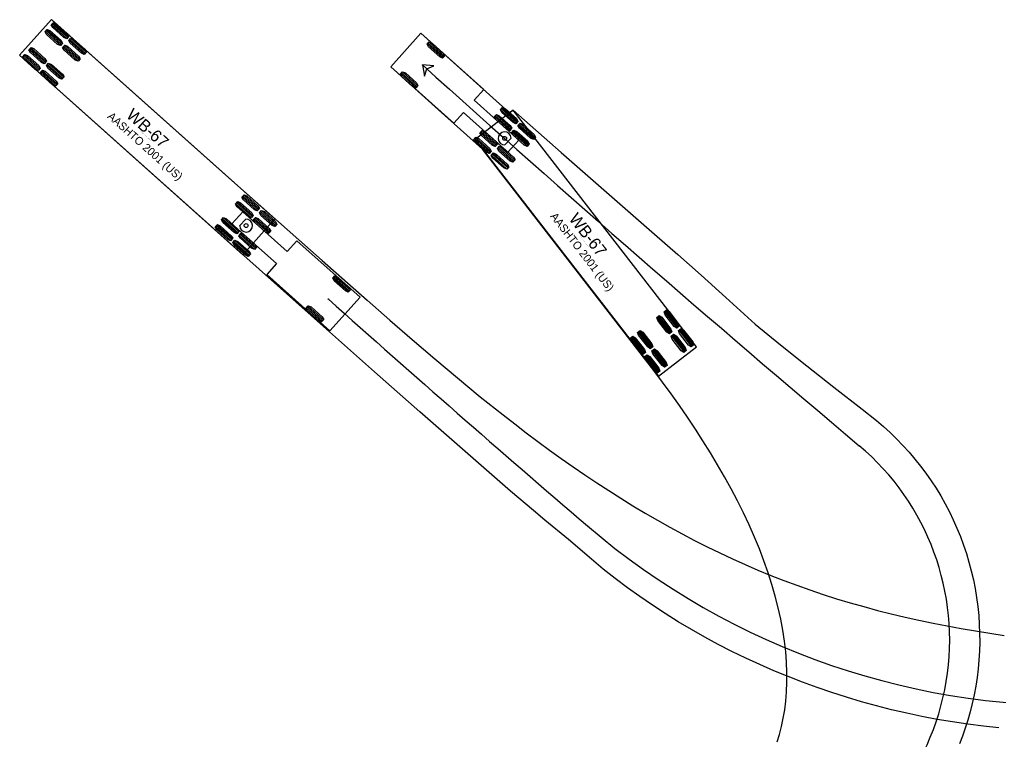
# Model space of a CAD drawing. Extents: x 1639988 to 1641860, y 841974 to 844187.
# Drawn here: x 1641375.4 to 1641548.8, y 842139 to 842266.5 of the extents above; entities that cross this region are included whole.
import ezdxf

# ---------------------------------------------------------------- set-up
doc = ezdxf.new("R2010")
doc.units = 0
doc.layers.add('Scratch_Level_1', color=7, linetype='Continuous')

msp = doc.modelspace()

# ---------------------------------------------------------------- linework, layer by layer
at = {"layer": 'Scratch_Level_1'}
for p, q in [((1641381.1, 842266.48), (1641375.43, 842260.15)), ((1641383.81, 842263.14), (1641381.07, 842265.58)), ((1641420.61, 842231.16), (1641381.1, 842266.48)), ((1641383.96, 842263.31), (1641381.23, 842265.75)), ((1641384.11, 842263.48), (1641381.38, 842265.92)), ((1641382.71, 842261.91), (1641379.97, 842264.35)), ((1641382.86, 842262.08), (1641380.13, 842264.52)), ((1641383.01, 842262.25), (1641380.28, 842264.69)), ((1641446.48, 842264.1), (1641441.14, 842258.14)), ((1641457.65, 842254.09), (1641446.48, 842264.1)), ((1641386.12, 842259.47), (1641383.38, 842261.92)), ((1641386.91, 842260.36), (1641384.18, 842262.81)), ((1641387.07, 842260.53), (1641384.33, 842262.98)), ((1641387.22, 842260.7), (1641384.48, 842263.15)), ((1641447.64, 842262.14), (1641450.36, 842259.69)), ((1641447.79, 842262.31), (1641450.51, 842259.86)), ((1641447.94, 842262.48), (1641450.67, 842260.03)), ((1641375.43, 842260.15), (1641414.94, 842224.82)), ((1641378.9, 842257.66), (1641376.17, 842260.1)), ((1641379.06, 842257.83), (1641376.32, 842260.27)), ((1641379.85, 842258.72), (1641377.12, 842261.16)), ((1641380, 842258.89), (1641377.27, 842261.33)), ((1641380.16, 842259.06), (1641377.42, 842261.5)), ((1641385.81, 842259.13), (1641383.08, 842261.58)), ((1641385.97, 842259.3), (1641383.23, 842261.75)), ((1641378.75, 842257.49), (1641376.02, 842259.93)), ((1641382.96, 842255.94), (1641380.22, 842258.38)), ((1641383.11, 842256.11), (1641380.38, 842258.55)), ((1641383.26, 842256.28), (1641380.53, 842258.72)), ((1641381.86, 842254.71), (1641379.12, 842257.15)), ((1641382.01, 842254.88), (1641379.28, 842257.32)), ((1641382.16, 842255.05), (1641379.43, 842257.49)), ((1641441.14, 842258.14), (1641452.31, 842248.13)), ((1641441.14, 842258.14), (1641441.14, 842258.14)), ((1641442.91, 842256.87), (1641445.63, 842254.41)), ((1641443.06, 842257.04), (1641445.78, 842254.58)), ((1641443.22, 842257.21), (1641445.94, 842254.75)), ((1641455.94, 842252.18), (1641457.65, 842254.09)), ((1641463.82, 842245.11), (1641455.94, 842252.18)), ((1641452.31, 842248.13), (1641454.02, 842250.04)), ((1641454.02, 842250.04), (1641461.91, 842242.98)), ((1641462.84, 842250.41), (1641456.11, 842245.21)), ((1641460.6, 842250.52), (1641463.34, 842248.07)), ((1641460.76, 842250.69), (1641463.49, 842248.24)), ((1641460.91, 842250.86), (1641463.64, 842248.41)), ((1641495.29, 842208.51), (1641462.84, 842250.41)), ((1641459.5, 842249.29), (1641462.23, 842246.84)), ((1641459.66, 842249.46), (1641462.39, 842247.01)), ((1641459.81, 842249.63), (1641462.54, 842247.18)), ((1641464.01, 842248.08), (1641466.75, 842245.63)), ((1641456.98, 842246.47), (1641459.71, 842244.02)), ((1641457.13, 842246.64), (1641459.86, 842244.19)), ((1641457.29, 842246.81), (1641460.02, 842244.37)), ((1641462.61, 842246.51), (1641465.34, 842244.06)), ((1641462.76, 842246.68), (1641465.49, 842244.23)), ((1641462.91, 842246.85), (1641465.64, 842244.4)), ((1641463.71, 842247.74), (1641466.44, 842245.29)), ((1641463.86, 842247.91), (1641466.59, 842245.46)), ((1641455.88, 842245.24), (1641458.61, 842242.79)), ((1641456.03, 842245.41), (1641458.76, 842242.97)), ((1641456.11, 842245.21), (1641488.57, 842203.3)), ((1641456.11, 842245.21), (1641456.11, 842245.21)), ((1641456.18, 842245.58), (1641458.92, 842243.14)), ((1641461.37, 842244.3), (1641462.45, 842245.5)), ((1641461.91, 842242.98), (1641463.82, 842245.11)), ((1641459.29, 842242.8), (1641462.02, 842240.36)), ((1641460.08, 842243.69), (1641462.81, 842241.24)), ((1641460.24, 842243.86), (1641462.97, 842241.41)), ((1641460.39, 842244.03), (1641463.12, 842241.59)), ((1641458.98, 842242.46), (1641461.71, 842240.01)), ((1641459.14, 842242.63), (1641461.87, 842240.19)), ((1641416.77, 842231.74), (1641414.03, 842234.18)), ((1641417.56, 842232.63), (1641414.83, 842235.07)), ((1641417.71, 842232.8), (1641414.98, 842235.24)), ((1641417.87, 842232.97), (1641415.13, 842235.41)), ((1641414.94, 842232.45), (1641413.03, 842230.31)), ((1641416.46, 842231.4), (1641413.73, 842233.84)), ((1641416.61, 842231.57), (1641413.88, 842234.01)), ((1641422.83, 842225.4), (1641414.94, 842232.45)), ((1641420.82, 842230.02), (1641418.09, 842232.47)), ((1641420.97, 842230.19), (1641418.24, 842232.64)), ((1641413.94, 842228.58), (1641411.21, 842231.02)), ((1641414.09, 842228.75), (1641411.36, 842231.19)), ((1641414.25, 842228.92), (1641411.51, 842231.36)), ((1641415.48, 842231.13), (1641414.4, 842229.93)), ((1641414.94, 842224.82), (1641420.61, 842231.16)), ((1641419.57, 842228.62), (1641416.83, 842231.07)), ((1641419.72, 842228.79), (1641416.99, 842231.24)), ((1641419.87, 842228.96), (1641417.14, 842231.41)), ((1641420.67, 842229.85), (1641417.93, 842232.3)), ((1641420.61, 842231.16), (1641420.61, 842231.16)), ((1641412.84, 842227.35), (1641410.11, 842229.79)), ((1641412.99, 842227.52), (1641410.26, 842229.96)), ((1641413.15, 842227.69), (1641410.41, 842230.13)), ((1641413.03, 842230.31), (1641420.92, 842223.26)), ((1641416.1, 842224.74), (1641413.37, 842227.19)), ((1641416.25, 842224.91), (1641413.52, 842227.36)), ((1641417.05, 842225.8), (1641414.31, 842228.24)), ((1641417.2, 842225.97), (1641414.47, 842228.42)), ((1641417.35, 842226.14), (1641414.62, 842228.59)), ((1641424.54, 842227.31), (1641422.83, 842225.4)), ((1641435.73, 842217.31), (1641424.54, 842227.31)), ((1641415.95, 842224.57), (1641413.21, 842227.01)), ((1641420.92, 842223.26), (1641419.21, 842221.35)), ((1641419.21, 842221.35), (1641430.39, 842211.35)), ((1641433.65, 842218.24), (1641430.92, 842220.69)), ((1641433.81, 842218.42), (1641431.07, 842220.86)), ((1641433.96, 842218.59), (1641431.22, 842221.03)), ((1641430.39, 842211.35), (1641435.73, 842217.31)), ((1641435.73, 842217.31), (1641435.73, 842217.31)), ((1641428.93, 842212.96), (1641426.2, 842215.41)), ((1641429.08, 842213.13), (1641426.35, 842215.58)), ((1641429.24, 842213.31), (1641426.5, 842215.75)), ((1641488.29, 842213.73), (1641490.53, 842210.83)), ((1641488.47, 842213.87), (1641490.71, 842210.97)), ((1641488.65, 842214.01), (1641490.89, 842211.11)), ((1641489.59, 842214.74), (1641491.84, 842211.84)), ((1641489.77, 842214.88), (1641492.02, 842211.98)), ((1641489.95, 842215.02), (1641492.2, 842212.12)), ((1641492.32, 842211.59), (1641494.57, 842208.69)), ((1641492.5, 842211.73), (1641494.75, 842208.83)), ((1641483.59, 842210.1), (1641485.84, 842207.2)), ((1641483.78, 842210.24), (1641486.02, 842207.34)), ((1641483.96, 842210.38), (1641486.2, 842207.48)), ((1641484.9, 842211.11), (1641487.14, 842208.21)), ((1641485.08, 842211.25), (1641487.33, 842208.35)), ((1641485.26, 842211.39), (1641487.51, 842208.49)), ((1641490.84, 842210.44), (1641493.08, 842207.54)), ((1641491.02, 842210.58), (1641493.26, 842207.68)), ((1641491.2, 842210.72), (1641493.44, 842207.82)), ((1641492.14, 842211.45), (1641494.39, 842208.55)), ((1641488.57, 842203.3), (1641495.29, 842208.51)), ((1641486.15, 842206.8), (1641488.39, 842203.91)), ((1641486.33, 842206.94), (1641488.57, 842204.05)), ((1641486.51, 842207.08), (1641488.75, 842204.19)), ((1641487.45, 842207.81), (1641489.7, 842204.92)), ((1641487.63, 842207.95), (1641489.88, 842205.06)), ((1641487.81, 842208.1), (1641490.06, 842205.2))]:
    msp.add_line(p, q, dxfattribs=at)
for points in [[(1641548.82, 842141.02), (1641546.09, 842141.31), (1641543.36, 842141.66), (1641540.64, 842142.06), (1641537.92, 842142.52), (1641535.21, 842143.04), (1641532.52, 842143.6), (1641529.83, 842144.23), (1641527.16, 842144.91), (1641524.5, 842145.64), (1641521.87, 842146.42), (1641519.24, 842147.26), (1641516.64, 842148.15), (1641514.07, 842149.1), (1641511.51, 842150.09), (1641508.99, 842151.13), (1641506.49, 842152.23), (1641504.02, 842153.37), (1641501.57, 842154.56), (1641499.15, 842155.8), (1641496.76, 842157.09), (1641494.4, 842158.42), (1641492.07, 842159.81), (1641489.77, 842161.24), (1641487.5, 842162.73), (1641485.27, 842164.26), (1641483.07, 842165.84), (1641480.91, 842167.46), (1641478.79, 842169.14), (1641476.7, 842170.87), (1641472.61, 842174.38), (1641468.46, 842177.78), (1641466.41, 842179.5), (1641462.35, 842182.97), (1641454.3, 842189.98), (1641446.28, 842197), (1641438.27, 842204.06), (1641430.28, 842211.15), (1641414.58, 842225.15), (1641375.43, 842260.15), (1641381.1, 842266.48), (1641381.21, 842266.38), (1641381.21, 842266.38)], [(1641381.21, 842266.38), (1641413.04, 842237.96), (1641428.98, 842223.8), (1641436.97, 842216.75), (1641440.97, 842213.25), (1641444.96, 842209.78), (1641448.96, 842206.36), (1641452.97, 842202.99), (1641457.01, 842199.68), (1641461.06, 842196.44), (1641463.1, 842194.86), (1641465.15, 842193.29), (1641467.2, 842191.75), (1641469.27, 842190.23), (1641471.34, 842188.74), (1641473.43, 842187.27), (1641475.53, 842185.83), (1641477.64, 842184.42), (1641479.76, 842183.03), (1641481.89, 842181.68), (1641484.03, 842180.35), (1641486.19, 842179.06), (1641488.36, 842177.8), (1641490.54, 842176.58), (1641492.74, 842175.38), (1641494.94, 842174.22), (1641497.16, 842173.1), (1641499.4, 842172.01), (1641501.64, 842170.96), (1641503.9, 842169.94), (1641506.17, 842168.97), (1641508.45, 842168.03), (1641510.74, 842167.13), (1641513.05, 842166.26), (1641515.38, 842165.44), (1641517.73, 842164.65), (1641520.1, 842163.89), (1641522.48, 842163.17), (1641524.89, 842162.48), (1641527.31, 842161.83), (1641529.75, 842161.22), (1641532.21, 842160.63), (1641534.68, 842160.08), (1641537.17, 842159.56), (1641539.67, 842159.07), (1641542.18, 842158.61), (1641544.7, 842158.18), (1641547.24, 842157.77), (1641549.79, 842157.39)], [(1641509.56, 842138.53), (1641509.97, 842139.86), (1641510.34, 842141.25), (1641510.65, 842142.7), (1641510.91, 842144.2), (1641511.1, 842145.76), (1641511.24, 842147.39), (1641511.31, 842149.08), (1641511.31, 842150.82), (1641511.24, 842152.62), (1641511.1, 842154.47), (1641510.88, 842156.36), (1641510.59, 842158.3), (1641510.22, 842160.28), (1641509.77, 842162.29), (1641509.24, 842164.33), (1641508.65, 842166.4), (1641507.98, 842168.48), (1641507.23, 842170.59), (1641506.42, 842172.7), (1641505.54, 842174.82), (1641504.6, 842176.95), (1641503.6, 842179.09), (1641502.54, 842181.22), (1641501.42, 842183.35), (1641500.25, 842185.48), (1641499.03, 842187.61), (1641497.76, 842189.72), (1641496.44, 842191.84), (1641495.09, 842193.94), (1641493.69, 842196.03), (1641492.26, 842198.12), (1641490.79, 842200.19), (1641489.29, 842202.26), (1641487.76, 842204.31), (1641457.41, 842243.54), (1641449.61, 842250.51), (1641441.14, 842258.14), (1641446.48, 842264.1), (1641462.14, 842250.05), (1641462.84, 842250.41), (1641471.32, 842242.96), (1641487.86, 842228.49), (1641491.99, 842224.87), (1641496.09, 842221.22), (1641500.5, 842217.27), (1641505.66, 842212.55), (1641510.18, 842208.87), (1641514.83, 842205.15), (1641519.63, 842201.35), (1641524.61, 842197.46), (1641527.15, 842195.45), (1641528.38, 842194.4), (1641529.58, 842193.31), (1641530.73, 842192.19), (1641531.85, 842191.04), (1641532.93, 842189.85), (1641533.97, 842188.63), (1641534.97, 842187.38), (1641535.92, 842186.1), (1641536.84, 842184.79), (1641537.71, 842183.45), (1641538.54, 842182.09), (1641539.33, 842180.69), (1641540.07, 842179.28), (1641540.76, 842177.84), (1641541.41, 842176.38), (1641542.02, 842174.9), (1641542.57, 842173.4), (1641543.08, 842171.88), (1641543.54, 842170.35), (1641543.95, 842168.8), (1641544.31, 842167.24), (1641544.63, 842165.68), (1641544.89, 842164.1), (1641545.1, 842162.52), (1641545.26, 842160.93), (1641545.36, 842159.34), (1641545.42, 842157.76), (1641545.43, 842156.17), (1641545.39, 842154.59), (1641545.3, 842153.02), (1641545.16, 842151.46), (1641544.97, 842149.91), (1641544.73, 842148.37), (1641544.45, 842146.85), (1641544.12, 842145.35), (1641543.75, 842143.86), (1641543.34, 842142.4), (1641542.88, 842140.96), (1641542.38, 842139.54), (1641541.85, 842138.16)], [(1641446.79, 842258.45), (1641447.15, 842256.48), (1641447.53, 842257.78), (1641448.78, 842258.29), (1641446.79, 842258.45)]]:
    msp.add_lwpolyline(points, dxfattribs=at)
for points in [[(1641384.15, 842263.52), (1641383.77, 842263.1), (1641383.27, 842263.31), (1641381.3, 842265.07), (1641381.03, 842265.54), (1641381.42, 842265.97), (1641381.91, 842265.75), (1641383.88, 842263.99)], [(1641383.05, 842262.29), (1641382.67, 842261.87), (1641382.17, 842262.08), (1641380.2, 842263.84), (1641379.94, 842264.31), (1641380.32, 842264.74), (1641380.81, 842264.52), (1641382.78, 842262.76)], [(1641386.16, 842259.52), (1641385.78, 842259.09), (1641385.28, 842259.3), (1641383.31, 842261.06), (1641383.04, 842261.53), (1641383.42, 842261.96), (1641383.92, 842261.75), (1641385.89, 842259.99)], [(1641387.26, 842260.75), (1641386.87, 842260.32), (1641386.38, 842260.53), (1641384.41, 842262.29), (1641384.14, 842262.76), (1641384.52, 842263.19), (1641385.02, 842262.98), (1641386.99, 842261.22)], [(1641447.6, 842262.1), (1641447.98, 842262.53), (1641448.48, 842262.31), (1641450.44, 842260.54), (1641450.7, 842260.07), (1641450.32, 842259.64), (1641449.82, 842259.86), (1641447.86, 842261.63)], [(1641379.1, 842257.87), (1641378.71, 842257.44), (1641378.22, 842257.66), (1641376.25, 842259.42), (1641375.98, 842259.89), (1641376.36, 842260.31), (1641376.86, 842260.1), (1641378.83, 842258.34)], [(1641380.2, 842259.1), (1641379.81, 842258.67), (1641379.32, 842258.89), (1641377.35, 842260.65), (1641377.08, 842261.12), (1641377.46, 842261.54), (1641377.96, 842261.33), (1641379.93, 842259.57)], [(1641383.3, 842256.32), (1641382.92, 842255.9), (1641382.42, 842256.11), (1641380.45, 842257.87), (1641380.19, 842258.34), (1641380.57, 842258.77), (1641381.07, 842258.55), (1641383.03, 842256.79)], [(1641446.79, 842258.45), (1641447.15, 842256.48), (1641447.53, 842257.78), (1641448.78, 842258.29)], [(1641382.2, 842255.09), (1641381.82, 842254.67), (1641381.32, 842254.88), (1641379.35, 842256.64), (1641379.09, 842257.11), (1641379.47, 842257.54), (1641379.97, 842257.32), (1641381.93, 842255.56)], [(1641442.87, 842256.83), (1641443.25, 842257.25), (1641443.75, 842257.04), (1641445.71, 842255.27), (1641445.97, 842254.79), (1641445.59, 842254.37), (1641445.09, 842254.59), (1641443.14, 842256.36)], [(1641460.57, 842250.48), (1641460.95, 842250.9), (1641461.45, 842250.69), (1641463.41, 842248.93), (1641463.68, 842248.45), (1641463.3, 842248.03), (1641462.8, 842248.24), (1641460.83, 842250)], [(1641459.47, 842249.25), (1641459.85, 842249.67), (1641460.34, 842249.46), (1641462.31, 842247.7), (1641462.58, 842247.23), (1641462.2, 842246.8), (1641461.7, 842247.01), (1641459.73, 842248.78)], [(1641463.67, 842247.7), (1641464.05, 842248.12), (1641464.55, 842247.91), (1641466.52, 842246.15), (1641466.78, 842245.67), (1641466.4, 842245.25), (1641465.9, 842245.46), (1641463.94, 842247.22)], [(1641456.94, 842246.43), (1641457.32, 842246.85), (1641457.82, 842246.64), (1641459.79, 842244.88), (1641460.05, 842244.41), (1641459.67, 842243.98), (1641459.18, 842244.2), (1641457.21, 842245.96)], [(1641462.57, 842246.47), (1641462.95, 842246.89), (1641463.45, 842246.68), (1641465.41, 842244.92), (1641465.68, 842244.45), (1641465.3, 842244.02), (1641464.8, 842244.23), (1641462.84, 842246)], [(1641455.84, 842245.2), (1641456.22, 842245.63), (1641456.72, 842245.41), (1641458.69, 842243.65), (1641458.95, 842243.18), (1641458.57, 842242.75), (1641458.07, 842242.97), (1641456.11, 842244.73)], [(1641458.94, 842242.42), (1641459.33, 842242.85), (1641459.82, 842242.63), (1641461.79, 842240.87), (1641462.06, 842240.4), (1641461.68, 842239.97), (1641461.18, 842240.19), (1641459.21, 842241.95)], [(1641460.05, 842243.65), (1641460.43, 842244.07), (1641460.92, 842243.86), (1641462.89, 842242.1), (1641463.16, 842241.63), (1641462.78, 842241.2), (1641462.28, 842241.42), (1641460.31, 842243.18)], [(1641416.81, 842231.78), (1641416.42, 842231.36), (1641415.93, 842231.57), (1641413.96, 842233.33), (1641413.69, 842233.8), (1641414.07, 842234.23), (1641414.57, 842234.01), (1641416.54, 842232.25)], [(1641417.9, 842233.01), (1641417.52, 842232.59), (1641417.03, 842232.8), (1641415.06, 842234.56), (1641414.79, 842235.03), (1641415.17, 842235.46), (1641415.67, 842235.24), (1641417.64, 842233.48)], [(1641421.01, 842230.24), (1641420.63, 842229.81), (1641420.13, 842230.02), (1641418.16, 842231.78), (1641417.9, 842232.25), (1641418.28, 842232.68), (1641418.78, 842232.47), (1641420.74, 842230.71)], [(1641414.28, 842228.96), (1641413.9, 842228.54), (1641413.41, 842228.75), (1641411.44, 842230.51), (1641411.17, 842230.98), (1641411.55, 842231.41), (1641412.05, 842231.19), (1641414.02, 842229.43)], [(1641419.91, 842229.01), (1641419.53, 842228.58), (1641419.03, 842228.79), (1641417.06, 842230.55), (1641416.8, 842231.02), (1641417.18, 842231.45), (1641417.68, 842231.24), (1641419.64, 842229.48)], [(1641413.18, 842227.73), (1641412.8, 842227.31), (1641412.31, 842227.52), (1641410.34, 842229.28), (1641410.07, 842229.75), (1641410.45, 842230.18), (1641410.95, 842229.96), (1641412.92, 842228.2)], [(1641416.29, 842224.96), (1641415.91, 842224.53), (1641415.41, 842224.74), (1641413.44, 842226.5), (1641413.18, 842226.97), (1641413.56, 842227.4), (1641414.05, 842227.19), (1641416.02, 842225.43)], [(1641417.39, 842226.19), (1641417.01, 842225.76), (1641416.51, 842225.97), (1641414.54, 842227.73), (1641414.28, 842228.2), (1641414.66, 842228.63), (1641415.15, 842228.42), (1641417.12, 842226.66)], [(1641434, 842218.63), (1641433.61, 842218.2), (1641433.12, 842218.42), (1641431.15, 842220.18), (1641430.88, 842220.65), (1641431.26, 842221.07), (1641431.76, 842220.86), (1641433.73, 842219.1)], [(1641429.28, 842213.35), (1641428.89, 842212.92), (1641428.4, 842213.13), (1641426.43, 842214.89), (1641426.16, 842215.36), (1641426.54, 842215.79), (1641427.04, 842215.58), (1641429.01, 842213.82)], [(1641489.55, 842214.71), (1641490, 842215.06), (1641490.45, 842214.76), (1641492.06, 842212.67), (1641492.24, 842212.16), (1641491.79, 842211.81), (1641491.34, 842212.11), (1641489.72, 842214.2)], [(1641488.24, 842213.7), (1641488.69, 842214.05), (1641489.14, 842213.75), (1641490.76, 842211.66), (1641490.94, 842211.15), (1641490.49, 842210.8), (1641490.04, 842211.1), (1641488.42, 842213.19)], [(1641492.1, 842211.41), (1641492.55, 842211.76), (1641493, 842211.46), (1641494.62, 842209.38), (1641494.79, 842208.86), (1641494.34, 842208.51), (1641493.89, 842208.81), (1641492.27, 842210.9)], [(1641483.55, 842210.06), (1641484, 842210.41), (1641484.45, 842210.11), (1641486.07, 842208.03), (1641486.25, 842207.51), (1641485.8, 842207.16), (1641485.34, 842207.47), (1641483.73, 842209.55)], [(1641484.85, 842211.07), (1641485.31, 842211.42), (1641485.76, 842211.12), (1641487.37, 842209.04), (1641487.55, 842208.53), (1641487.1, 842208.18), (1641486.65, 842208.48), (1641485.03, 842210.56)], [(1641490.79, 842210.4), (1641491.24, 842210.75), (1641491.7, 842210.45), (1641493.31, 842208.37), (1641493.49, 842207.85), (1641493.04, 842207.5), (1641492.59, 842207.8), (1641490.97, 842209.89)], [(1641487.41, 842207.78), (1641487.86, 842208.13), (1641488.31, 842207.83), (1641489.93, 842205.74), (1641490.1, 842205.23), (1641489.65, 842204.88), (1641489.2, 842205.18), (1641487.58, 842207.27)], [(1641486.1, 842206.77), (1641486.55, 842207.12), (1641487, 842206.82), (1641488.62, 842204.73), (1641488.8, 842204.22), (1641488.35, 842203.87), (1641487.9, 842204.17), (1641486.28, 842206.26)]]:
    msp.add_lwpolyline(points, close=True, dxfattribs=at)
for centre, radius in [((1641446.79, 842258.45), 0.0417), ((1641461.31, 842245.44), 0.34), ((1641415.54, 842229.99), 0.34), ((1641430.08, 842217), 0.0417), ((1641524.11, 842191), 0.0417), ((1641524.11, 842191), 0.0417), ((1641475.97, 842176.8), 0.0417), ((1641475.97, 842176.8), 0.0417)]:
    msp.add_circle(centre, radius, dxfattribs=at)
for centre, radius, start, end in [((1643441.46, 844467.03), 2976, 227.9133, 229.88883), ((1641461.31, 842245.44), 1.14, 3.149, 273.149), ((1641415.54, 842229.99), 1.14, 183.2053, 93.2053), ((1643441.46, 844467.03), 3018, 228.20534, 229.36348), ((1641495.12, 842156.58), 45, 291.2884, 49.8888), ((1641561.93, 842276.97), 132, 229.3635, 272.836)]:
    msp.add_arc(centre, radius, start, end, dxfattribs=at)

# ---------------------------------------------------------------- texts
for s, height, rotation, p in [('AASHTO 2001 (US)', 1.4167, 318.2053, (1641390.88, 842249.17)), ('WB-67', 2.125, 318.2053, (1641394.17, 842249.32)), ('(c) 2019 Transoft Solutions, Inc. All rights reserved.', 0.085, 318.2053, (1641396.7, 842246.78)), ('WB-67', 2.125, 307.7568, (1641472.58, 842231.16)), ('AASHTO 2001 (US)', 1.4167, 307.7568, (1641469.32, 842231.61)), ('(c) 2019 Transoft Solutions, Inc. All rights reserved.', 0.085, 307.7568, (1641474.61, 842228.2))]:
    msp.add_text(s, height=height, rotation=rotation, dxfattribs=at).set_placement(p)

doc.saveas('drawing.dxf')
